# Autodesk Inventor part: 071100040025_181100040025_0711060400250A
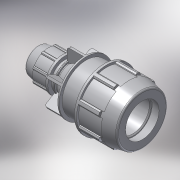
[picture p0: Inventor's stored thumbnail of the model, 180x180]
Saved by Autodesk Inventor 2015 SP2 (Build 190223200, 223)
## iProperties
Created: 2017-02
Part Number: 071100040025_181100040025_0711060400250A
Material: PVC-Piping
Description: PLASSON REDUCING COUPLER 40-25
Document SubType Name: Modeling
Designer: KIM
Mass: 92.6774 g
Surface Area: 199.44 cm^2
Volume: 66.1981 cm^3
Density: 1.4 g/cm^3
Appearance: Smooth - White
Author: KIM
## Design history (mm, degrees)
derived "07110.ipt"
feature "Solid1::07110.ipt"
tag "TaggingFeature1"
body "Solid1"
other parameters: "d4" = 13, "d5" = 22.28571, "d7" = 82, "d9" = 22.28571, "d11" = 2.22857, "d12" = 65.6, "d13" = 120 deg, "d15" = 12 deg, "d16" = 73.8, "d18" = 2, "d19" = 35 deg, "d20" = 17.5 deg, "d21" = 76.26, "d23" = 0, "d25" = 360 deg, "d27" = 1.64, "d42" = 34.32, "d46" = 1.2, "d51" = 156, "d52" = 22.28571, "d53" = 12 deg, "d54" = 84, "d56" = 37.5, "d57" = 25, "d58" = 36, "d59" = 22.5, "d60" = 48.6, "d61" = 43.2, "d62" = 15.6, "d63" = 24.96, "d64" = 120 deg, "d65" = 54, "d68" = 11.14286, "d74" = 50.22, "d75" = 35 deg, "d76" = 17.5 deg, "d78" = 0, "d80" = 360 deg, "d85" = 1.08, "d88" = 0.5, "d93" = 58, "d94" = 57.4, "d97" = 3.15, "d98" = 3.6, "d99" = 0, "d100" = 3.28, "d102" = 360 deg, "d104" = 2, "d106" = 0, "d107" = 3.6, "d108" = 0, "d109" = 3.6, "d110" = 0, "E_" = 82, "H_" = 156, "l_" = 84, "d_1" = 25, "E_1" = 54, "l_1" = 58, "d96" = 9.45
